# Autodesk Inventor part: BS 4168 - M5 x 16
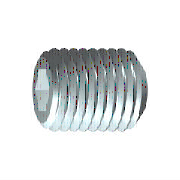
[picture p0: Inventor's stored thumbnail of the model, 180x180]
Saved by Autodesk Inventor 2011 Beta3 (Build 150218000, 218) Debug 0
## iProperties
IsCustomPart: 0
Created: 2008-01
Part Number: BS 4168 - M5 x 16
Material: Steel, Mild
Description: Hexagon socket screws and wrench keys, metric series- Specification for hexagon set screws with flat point
Document SubType Name: Modeling
Standard: BS 4168
Designer: latalom
Standards Organization: BSI
Language: en-US
Size Designation: M5 x 16
Categories: <MemberInstance><Categories><Category DisplayName="Fasteners" InternalName="e4da775c-781d-43d5-af7c-5136215cf5a6" Mnemonic="FSTN"><Category DisplayName="Bolts"
Density: 7.86 g/cm^3
Mass: 2.29997 g
Surface Area: 3.08393 cm^2
Volume: 0.292617 cm^3
Author: latalom
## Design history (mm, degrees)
revolve "Body" stored, may be unused: angle "d6" = 90 deg
sketch "Sketch2"
  geometry: L1 (-0.722, 1.25)-(0.722, 1.25); L2 (0.722, 1.25)-(1.443, 0); L3 (1.443, 0)-(0.722, -1.25); L4 (0.722, -1.25)-(-0.722, -1.25); L5 (-0.722, -1.25)-(-1.443, 0); L6 (-1.443, 0)-(-0.722, 1.25); A1 r 1.443 centre (0, 0) between (-0.722, 1.25) and (0.722, 1.25) reference; 2 further points
  constraints: 12 end point, 2 point on circle, 1 coincident, 1 horizontal, 11 other
extrude "Slot" join sketch "Sketch2" taper "d9" = 0 deg; stored distance "d21" = 10
workaxis "Work Axis1"
workplane "Work Plane1"
body "Solid1"
chamfer "Chamfer1" distance "d7" = 0.49076 (= -0.5 x GD1 + 0.5 x NND); stored, may be unused: angle "d8" = 45 deg (= FAWI), second distance "d29" = 0.49076 (= -0.5 x GD1 + 0.5 x NND)
feature "Thread" dims "d11" = 16 (= NLG), "d12" = 0
chamfer "Chamfer2" distance "d13" = 0.49076 (= -0.5 x GD1 + 0.5 x NND); stored, may be unused: angle "d14" = 45 deg (= FAWI), second distance "d30" = 0.49076 (= -0.5 x GD1 + 0.5 x NND)
sketch "Sketch1"
  geometry: L1 (0, 0)-(12.167, 0); L2 (16, 1.443)-(16, 2.5); L3 (16, 2.5)-(0, 2.5); L4 (16, 1.443)-(13, 1.443); L5 (13, 1.443)-(12.167, 0); L6 (0, -0.5)-(0, 3) reference; L7 (0, 2.5)-(0, 0)
  constraints: 13 end point, 3 parallel, 1 collinear, 1 perpendicular, 1 point on line
  dimensions: "d0" = 3 distance of L2.start L4.end (= INTI); "d1" = 60 deg angle of L5 L1; "d2" = 5 diameter of L3 L1 (= NND); "d3" = 2.88675 diameter of L4 L1 (= 1.1547 x SW); "d5" = 16 distance from line of L2 L3.end (= NLG)
other parameters: "NND" = 5 [user parameter; used in 5 equation terms], "NLG" = 16 [user parameter; used in 2 equation terms], "INTI" = 3 [user parameter; used in 1 equation term], "FAWI" = 45 deg [user parameter; used in 2 equation terms], "SW" = 2.5 [user parameter; used in 2 equation terms], "GD1" = 4.01848 (= THREADDIA - 1.2269 x PTC) [user parameter; used in 4 equation terms], "d4" = 0, "FAWI1" = 45 deg [user parameter], "d15" = 0, "d31" = 0, "GUL" = 0.49076 (= 0.61345 x PTC) [user parameter], "SPD" = 3.5 [user parameter], "TPU" = 12.5 (computed from PTC) [user parameter], "TOA" = 30 deg [user parameter], "THREADDIA" = 5 [user parameter; used in 1 equation term], "PTC" = 0.8 [user parameter; used in 4 equation terms], "GAL" = 0.49076 (= 0.61345 x PTC) [user parameter], "E0" = 2.8875 (= 1.155 x SW) [user parameter]
